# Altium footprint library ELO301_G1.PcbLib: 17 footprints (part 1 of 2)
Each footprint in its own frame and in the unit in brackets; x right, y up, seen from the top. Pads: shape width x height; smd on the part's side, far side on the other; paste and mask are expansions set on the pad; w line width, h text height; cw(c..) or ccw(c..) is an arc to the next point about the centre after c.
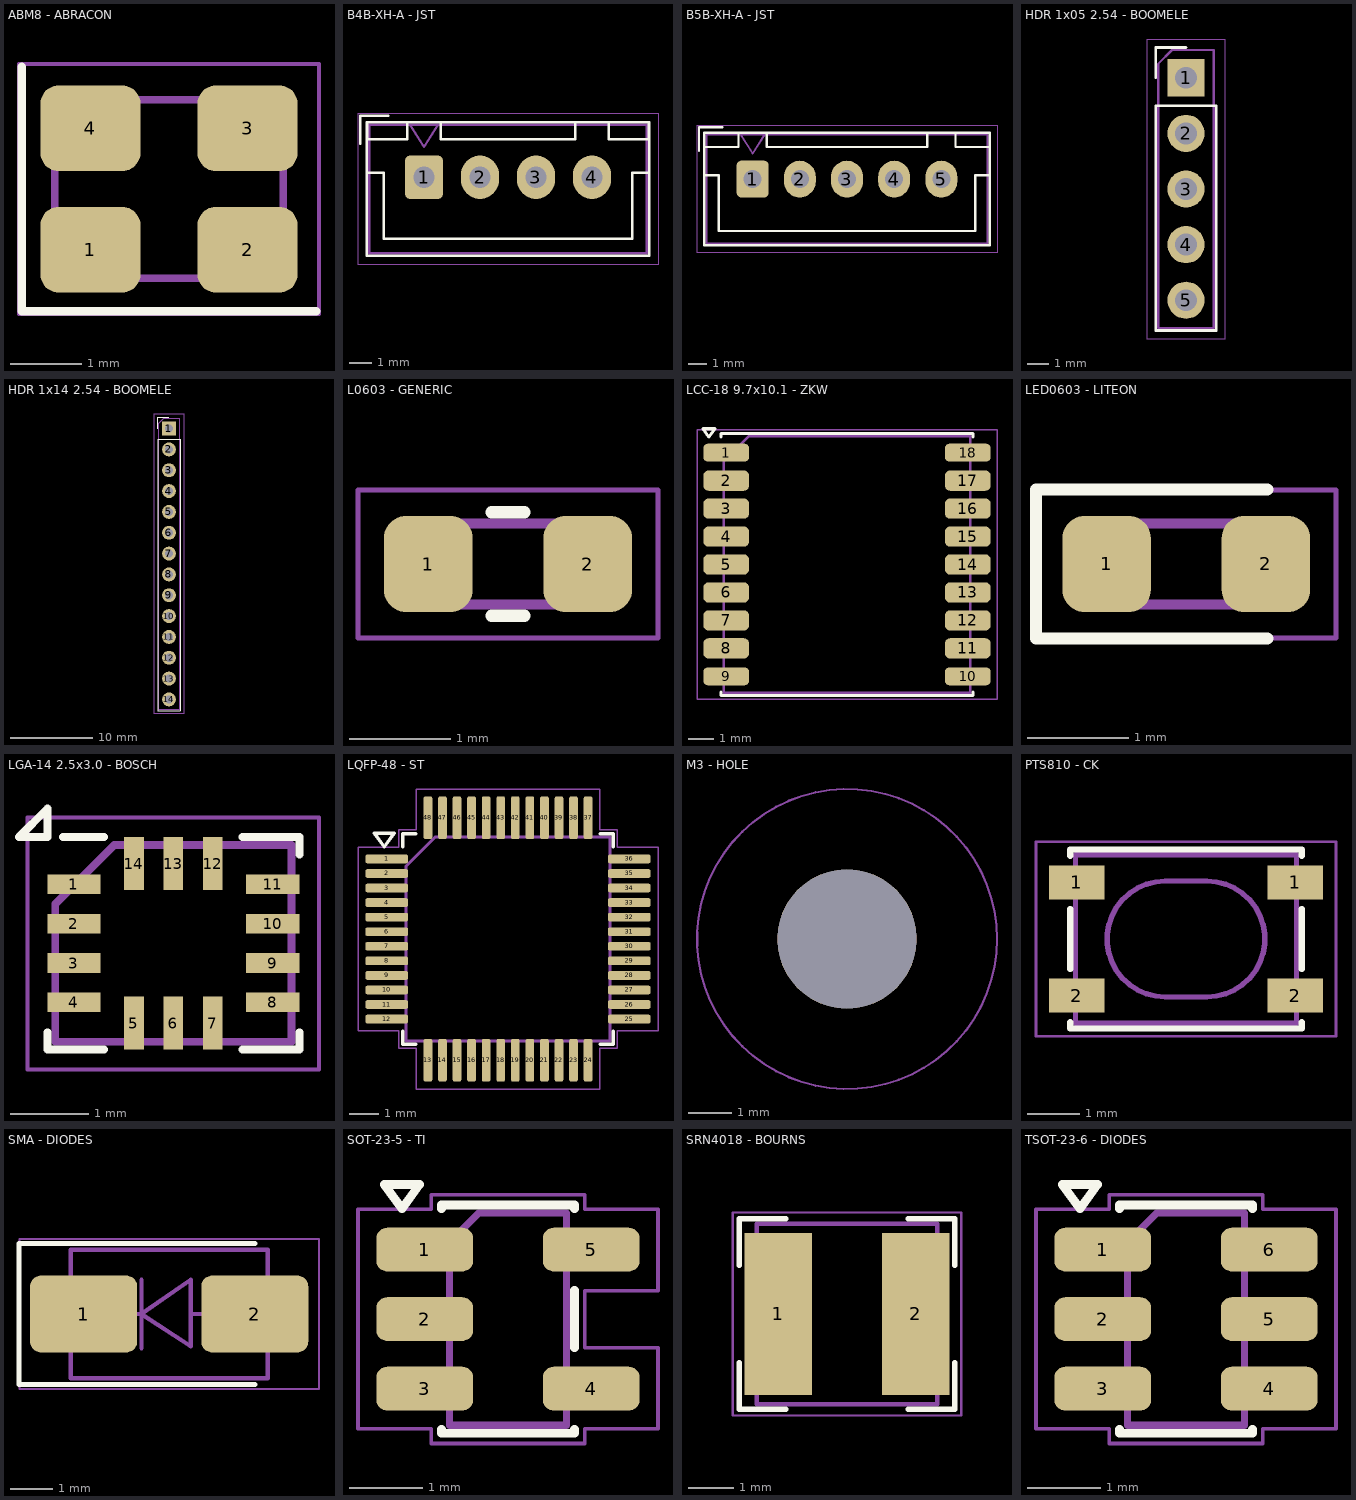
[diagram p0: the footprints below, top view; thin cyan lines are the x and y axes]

## ABM8 - ABRACON [mm] "Abracon ABM8G, Miniature Ceramic Crystal, 3.2x2.5mm package, SMD, http://www.abracon.com/Resonators/ABM8G.pdf"
pads (4):
  rrect42% 1.4x1.2 smd: 1(1268.9,1269.15) 2(1271.1,1269.15) 3(1271.1,1270.85) 4(1268.9,1270.85)
Top Overlay:
  lines w0.12: 1267.94,1271.71 1267.94,1268.29 1272.06,1268.29
Mechanical 13:
  lines w0.1: 1268.4,1269.375 1269.025,1268.75 1271.6,1268.75 1271.6,1271.25 1268.4,1271.25 1268.4,1269.375
Mechanical 15:
  lines w0.05: 1267.9,1268.25 1272.1,1268.25 1272.1,1271.75 1267.9,1271.75 1267.9,1268.25
Mechanical 29:
  text ".Designator" at 1269.492,1269.898 h0.25

## B4B-XH-A - JST [mm] "JST XH series connector, B4B-XH-A (http://www.jst-mfg.com/product/pdf/eng/eXH.pdf)"
pads (4):
  rrect29% 1.7x1.95 hole 0.95: 1(1270,1270)
  oval 1.7x1.95 hole 0.95: 2(1272.5,1270) 3(1275,1270) 4(1277.5,1270)
Top Overlay:
  lines w0.12: 1267.15,1271.5 1267.15,1272.75 1268.4,1272.75 ; 1267.45,1270.2 1268.2,1270.2 1268.2,1267.25 1273.75,1267.25 1279.3,1267.25 1279.3,1270.2 1280.05,1270.2 ; 1267.44,1266.49 1280.06,1266.49 1280.06,1272.46 1267.44,1272.46 1267.44,1266.49 ; 1267.45,1271.7 1269.25,1271.7 1269.25,1272.45 1267.45,1272.45 1267.45,1271.7 ; 1270.75,1271.7 1276.75,1271.7 1276.75,1272.45 1270.75,1272.45 1270.75,1271.7 ; 1278.25,1271.7 1280.05,1271.7 1280.05,1272.45 1278.25,1272.45 1278.25,1271.7
Mechanical 13:
  lines w0.1: 1269.375,1272.35 1270,1271.35 1270.625,1272.35 ; 1267.55,1266.6 1279.95,1266.6 1279.95,1272.35 1267.55,1272.35 1267.55,1266.6
Mechanical 15:
  lines w0.05: 1267.05,1266.1 1280.45,1266.1 1280.45,1272.85 1267.05,1272.85 1267.05,1266.1
Mechanical 29:
  text ".Designator" at 1269.492,1269.898 h0.25

## B5B-XH-A - JST [mm] "JST XH series connector, B5B-XH-A (http://www.jst-mfg.com/product/pdf/eng/eXH.pdf)"
pads (5):
  rrect29% 1.7x1.95 hole 0.95: 1(1270,1270)
  oval 1.7x1.95 hole 0.95: 2(1272.5,1270) 3(1275,1270) 4(1277.5,1270) 5(1280,1270)
Top Overlay:
  lines w0.12: 1267.15,1271.5 1267.15,1272.75 1268.4,1272.75 ; 1267.45,1270.2 1268.2,1270.2 1268.2,1267.25 1275,1267.25 1281.8,1267.25 1281.8,1270.2 1282.55,1270.2 ; 1267.44,1266.49 1282.56,1266.49 1282.56,1272.46 1267.44,1272.46 1267.44,1266.49 ; 1267.45,1271.7 1269.25,1271.7 1269.25,1272.45 1267.45,1272.45 1267.45,1271.7 ; 1270.75,1271.7 1279.25,1271.7 1279.25,1272.45 1270.75,1272.45 1270.75,1271.7 ; 1280.75,1271.7 1282.55,1271.7 1282.55,1272.45 1280.75,1272.45 1280.75,1271.7
Mechanical 13:
  lines w0.1: 1269.375,1272.35 1270,1271.35 1270.625,1272.35 ; 1267.55,1266.6 1282.45,1266.6 1282.45,1272.35 1267.55,1272.35 1267.55,1266.6
Mechanical 15:
  lines w0.05: 1267.05,1266.1 1282.95,1266.1 1282.95,1272.85 1267.05,1272.85 1267.05,1266.1
Mechanical 29:
  text ".Designator" at 1269.492,1269.898 h0.25

## HDR 1x05 2.54 - BOOMELE [mm] "Through hole straight pin header, 1x05, 2.54mm pitch, single row"
pads (5):
  rect 1.7x1.7 hole 1: 1(1270,1270)
  round 1.7 hole 1: 2(1270,1267.46) 3(1270,1264.92) 4(1270,1262.38) 5(1270,1259.84)
Top Overlay:
  lines w0.12: 1268.62,1270 1268.62,1271.38 1270,1271.38 ; 1268.62,1258.46 1268.62,1268.73 1271.38,1268.73 1271.38,1258.46 1268.62,1258.46
Mechanical 13:
  lines w0.1: 1268.73,1258.57 1268.73,1270.635 1269.365,1271.27 1271.27,1271.27 1271.27,1258.57 1268.73,1258.57
Mechanical 15:
  lines w0.05: 1268.23,1258.07 1271.77,1258.07 1271.77,1271.77 1268.23,1271.77 1268.23,1258.07
Mechanical 29:
  text ".Designator" at 1269.492,1269.898 h0.25

## HDR 1x14 2.54 - BOOMELE [mm] "Through hole straight pin header, 1x14, 2.54mm pitch, single row"
pads (14):
  rect 1.7x1.7 hole 1: 1(1270,1270)
  round 1.7 hole 1: 2(1270,1267.46) 3(1270,1264.92) 4(1270,1262.38) 5(1270,1259.84) 6(1270,1257.3) 7(1270,1254.76) 8(1270,1252.22) 9(1270,1249.68) 10(1270,1247.14) 11(1270,1244.6) 12(1270,1242.06) 13(1270,1239.52) 14(1270,1236.98)
Top Overlay:
  lines w0.12: 1268.62,1270 1268.62,1271.38 1270,1271.38 ; 1268.62,1235.6 1268.62,1268.73 1271.38,1268.73 1271.38,1235.6 1268.62,1235.6
Mechanical 13:
  lines w0.1: 1268.73,1235.71 1268.73,1270.635 1269.365,1271.27 1271.27,1271.27 1271.27,1235.71 1268.73,1235.71
Mechanical 15:
  lines w0.05: 1268.23,1235.2 1271.77,1235.2 1271.77,1271.78 1268.23,1271.78 1268.23,1235.2
Mechanical 29:
  text ".Designator" at 1269.492,1269.898 h0.25

## L0603 - GENERIC [mm] "Inductor SMD 0603 (1608 Metric), square (rectangular) end terminal, IPC-7351 nominal, (Body size source: http://www.tortai-tech.com/upload/download/2011102023233369053.pdf)"
pads (2):
  rrect50% 0.875x0.95 smd: 1(1269.212,1270) 2(1270.788,1270)
Top Overlay:
  lines w0.12: 1269.837,1269.49 1270.163,1269.49 ; 1269.837,1270.51 1270.163,1270.51
Mechanical 13:
  lines w0.1: 1269.2,1269.6 1270.8,1269.6 1270.8,1270.4 1269.2,1270.4 1269.2,1269.6
Mechanical 15:
  lines w0.05: 1268.52,1269.27 1271.48,1269.27 1271.48,1270.73 1268.52,1270.73 1268.52,1269.27
Mechanical 29:
  text ".Designator" at 1269.492,1269.898 h0.25

## LCC-18 9.7x10.1 - ZKW [mm] "ublox MAX 6/7/8, (https://www.u-blox.com/sites/default/files/MAX-8-M8-FW3_HardwareIntegrationManual_%28UBX-15030059%29.pdf)"
pads (18):
  rrect50% 1.8x0.7 smd: 1(1265.25,1274.4) 9(1265.25,1265.6) 10(1274.75,1265.6) 18(1274.75,1274.4)
  rrect50% 1.8x0.8 smd: 2(1265.25,1273.3) 3(1265.25,1272.2) 4(1265.25,1271.1) 5(1265.25,1270) 6(1265.25,1268.9) 7(1265.25,1267.8) 8(1265.25,1266.7) 11(1274.75,1266.7) 12(1274.75,1267.8) 13(1274.75,1268.9) 14(1274.75,1270) 15(1274.75,1271.1) 16(1274.75,1272.2) 17(1274.75,1273.3)
Top Overlay:
  lines w0.12: 1265.04,1264.99 1265.04,1264.84 1274.96,1264.84 1274.96,1264.99 ; 1265.04,1275.01 1265.04,1275.16 1274.96,1275.16 1274.96,1275.01 ; 1264.57,1275.01 1264.33,1275.34 1264.81,1275.34 1264.57,1275.01 ; 1264.57,1275.01 1264.57,1275.01
Mechanical 13:
  lines w0.1: 1265.15,1264.95 1265.15,1274.05 1266.15,1275.05 1274.85,1275.05 1274.85,1264.95 1265.15,1264.95
Mechanical 15:
  lines w0.05: 1264.1,1264.7 1264.1,1275.3 1275.9,1275.3 1275.9,1264.7 1264.1,1264.7
Mechanical 29:
  text ".Designator" at 1269.492,1269.898 h0.25

## LED0603 - LITEON [mm] "LED SMD 0603 (1608 Metric), square (rectangular) end terminal, IPC-7351 nominal, (Body size source: http://www.tortai-tech.com/upload/download/2011102023233369053.pdf)"
pads (2):
  rrect50% 0.875x0.95 smd: 1(1269.212,1270) 2(1270.788,1270)
Top Overlay:
  lines w0.12: 1270.8,1269.265 1268.515,1269.265 1268.515,1270.735 1270.8,1270.735
Mechanical 13:
  lines w0.1: 1269.2,1269.6 1269.2,1270.1 1269.5,1270.4 1270.8,1270.4 1270.8,1269.6 1269.2,1269.6
Mechanical 15:
  lines w0.05: 1268.52,1269.27 1271.48,1269.27 1271.48,1270.73 1268.52,1270.73 1268.52,1269.27
Mechanical 29:
  text ".Designator" at 1269.492,1269.898 h0.25

## LGA-14 2.5x3.0 - BOSCH [mm] "LGA-14 Bosch https://ae-bst.resource.bosch.com/media/_tech/media/datasheets/BST-BMI160-DS000-07.pdf"
pads (14):
  rect 0.675x0.25 smd: 1(1268.737,1270.75) 2(1268.737,1270.25) 3(1268.737,1269.75) 4(1268.737,1269.25) 8(1271.263,1269.25) 9(1271.263,1269.75) 10(1271.263,1270.25) 11(1271.263,1270.75)
  rect 0.25x0.675 smd: 5(1269.5,1268.988) 6(1270,1268.988) 7(1270.5,1268.988) 12(1270.5,1271.012) 13(1270,1271.012) 14(1269.5,1271.012)
Top Overlay:
  lines w0.1: 1268.4,1268.87 1268.4,1268.65 1269.12,1268.65 ; 1268.6,1271.35 1269.12,1271.35 ; 1270.88,1268.65 1271.6,1268.65 1271.6,1268.87 ; 1270.88,1271.35 1271.6,1271.35 1271.6,1271.13 ; 1268.4,1271.35 1268.04,1271.35 1268.4,1271.71 1268.4,1271.35 ; 1268.4,1271.35 1268.4,1271.35
Mechanical 13:
  lines w0.1: 1268.5,1268.75 1268.5,1270.5 1269.25,1271.25 1271.5,1271.25 1271.5,1268.75 1268.5,1268.75
Mechanical 15:
  lines w0.05: 1268.15,1268.4 1268.15,1271.6 1271.85,1271.6 1271.85,1268.4 1268.15,1268.4
Mechanical 29:
  text ".Designator" at 1269.492,1269.898 h0.25

## LQFP-48 - ST [mm] "LQFP, 48 Pin (JEDEC MS-026 variation BBC, 1.40mm body thickness, https://www.jedec.org/document_search?search_api_views_fulltext=MS-026, https://www.analog.com/media/en/package-pcb-resources/package/pkg_pdf/ltc-legacy-lqfp/05081760_a_lx48.pdf)"
pads (48):
  rrect50% 1.475x0.3 smd: 1(1265.837,1272.75) 2(1265.837,1272.25) 3(1265.837,1271.75) 4(1265.837,1271.25) 5(1265.837,1270.75) 6(1265.837,1270.25) 7(1265.837,1269.75) 8(1265.837,1269.25) 9(1265.837,1268.75) 10(1265.837,1268.25) 11(1265.837,1267.75) 12(1265.837,1267.25) 25(1274.163,1267.25) 26(1274.163,1267.75) 27(1274.163,1268.25) 28(1274.163,1268.75) 29(1274.163,1269.25) 30(1274.163,1269.75) 31(1274.163,1270.25) 32(1274.163,1270.75) 33(1274.163,1271.25) 34(1274.163,1271.75) 35(1274.163,1272.25) 36(1274.163,1272.75)
  rrect50% 0.3x1.475 smd: 13(1267.25,1265.837) 14(1267.75,1265.837) 15(1268.25,1265.837) 16(1268.75,1265.837) 17(1269.25,1265.837) 18(1269.75,1265.837) 19(1270.25,1265.837) 20(1270.75,1265.837) 21(1271.25,1265.837) 22(1271.75,1265.837) 23(1272.25,1265.837) 24(1272.75,1265.837) 37(1272.75,1274.163) 38(1272.25,1274.163) 39(1271.75,1274.163) 40(1271.25,1274.163) 41(1270.75,1274.163) 42(1270.25,1274.163) 43(1269.75,1274.163) 44(1269.25,1274.163) 45(1268.75,1274.163) 46(1268.25,1274.163) 47(1267.75,1274.163) 48(1267.25,1274.163)
Top Overlay:
  lines w0.12: 1266.39,1266.84 1266.39,1266.39 1266.84,1266.39 ; 1266.39,1273.16 1266.39,1273.61 1266.84,1273.61 ; 1273.16,1266.39 1273.61,1266.39 1273.61,1266.84 ; 1273.16,1273.61 1273.61,1273.61 1273.61,1273.16 ; 1265.41,1273.63 1266.09,1273.63 1265.75,1273.16 1265.41,1273.63
Mechanical 13:
  lines w0.1: 1266.5,1266.5 1266.5,1272.5 1267.5,1273.5 1273.5,1273.5 1273.5,1266.5 1266.5,1266.5
Mechanical 15:
  lines w0.05: 1264.85,1266.85 1266.25,1266.85 1266.25,1266.25 1266.85,1266.25 1266.85,1264.85 1273.15,1264.85 1273.15,1266.25 1273.75,1266.25 1273.75,1266.85 1275.15,1266.85 1275.15,1273.15 1273.75,1273.15 1273.75,1273.75 1273.15,1273.75 1273.15,1275.15 1266.85,1275.15 1266.85,1273.75 1266.25,1273.75 1266.25,1273.15 1264.85,1273.15 1264.85,1266.85
Mechanical 29:
  text ".Designator" at 1269.492,1269.898 h0.25

## M3 - HOLE [mm] "Mounting Hole 3.2mm, M3, no annular, generated by kicad-footprint-generator mountinghole.py"
pads (1):
  round 3.2 hole 3.2 unplated: ""(1270,1270)
Mechanical 15:
  circle w0.05: c1270,1270 r3.45
Mechanical 29:
  text ".Designator" at 1269.492,1269.898 h0.25

## PTS810 - CK [mm] "C&K Components, PTS 810 Series, Microminiature SMT Top Actuated, http://www.ckswitches.com/media/1476/pts810.pdf"
pads (4):
  rect 1.05x0.65 smd: 1(1267.925,1271.075) 1(1272.075,1271.075) 2(1267.925,1268.925) 2(1272.075,1268.925)
Top Overlay:
  lines w0.12: 1267.8,1268.42 1267.8,1268.3 1272.2,1268.3 1272.2,1268.42 ; 1267.8,1269.43 1267.8,1270.57 ; 1267.8,1271.58 1267.8,1271.7 1272.2,1271.7 1272.2,1271.58 ; 1272.2,1269.43 1272.2,1270.57
Mechanical 13:
  lines w0.1: 1267.9,1268.4 1267.9,1271.6 1272.1,1271.6 1272.1,1268.4 1267.9,1268.4 ; 1269.6,1268.9 1270.4,1268.9 ccw(c1270.4,1270) 1270.4,1271.1 1269.6,1271.1 ccw(c1269.6,1270) 1269.6,1268.9
Mechanical 15:
  lines w0.05: 1267.15,1268.15 1267.15,1271.85 1272.85,1271.85 1272.85,1268.15 1267.15,1268.15
Mechanical 29:
  text ".Designator" at 1269.492,1269.898 h0.25

## SMA - DIODES [mm] "Diode SMA (DO-214AC)"
pads (2):
  rrect28% 2.5x1.8 smd: 1(1268,1270) 2(1272,1270)
Top Overlay:
  lines w0.12: 1272,1268.35 1266.49,1268.35 1266.49,1271.65 1272,1271.65
Mechanical 13:
  lines w0.1: 1268.449,1269.999 1269.351,1269.999 ; 1269.351,1269.199 1269.351,1270.799 ; 1270.501,1269.999 1271.499,1269.999 ; 1269.351,1269.999 1270.501,1270.799 1270.501,1269.25 1269.351,1269.999 ; 1267.7,1268.5 1267.7,1271.5 1272.3,1271.5 1272.3,1268.5 1267.7,1268.5
Mechanical 15:
  lines w0.05: 1266.5,1268.25 1266.5,1271.75 1273.5,1271.75 1273.5,1268.25 1266.5,1268.25
Mechanical 29:
  text ".Designator" at 1269.492,1269.898 h0.25

## SOT-23-5 - TI [mm] "SOT, 5 Pin (JEDEC MO-178 Var AA https://www.jedec.org/document_search?search_api_views_fulltext=MO-178)"
pads (5):
  rrect50% 1.325x0.6 smd: 1(1268.863,1270.95) 2(1268.863,1270) 3(1268.863,1269.05) 4(1271.137,1269.05) 5(1271.137,1270.95)
Top Overlay:
  lines w0.12: 1269.09,1268.49 1269.09,1268.44 1270.91,1268.44 1270.91,1268.49 ; 1269.09,1271.51 1269.09,1271.56 1270.91,1271.56 1270.91,1271.51 ; 1270.91,1269.61 1270.91,1270.39 ; 1268.31,1271.84 1268.55,1271.51 1268.79,1271.84 1268.31,1271.84
Mechanical 13:
  lines w0.1: 1269.2,1268.55 1270.8,1268.55 1270.8,1271.45 1269.6,1271.45 1269.2,1271.05 1269.2,1268.55
Mechanical 15:
  lines w0.05: 1267.95,1268.5 1267.95,1271.5 1268.95,1271.5 1268.95,1271.7 1271.05,1271.7 1271.05,1271.5 1272.05,1271.5 1272.05,1270.39 1271.05,1270.39 1271.05,1269.61 1272.05,1269.61 1272.05,1268.5 1271.05,1268.5 1271.05,1268.3 1268.95,1268.3 1268.95,1268.5 1267.95,1268.5
Mechanical 29:
  text ".Designator" at 1269.492,1269.898 h0.25

## SRN4018 - BOURNS [mm] "Bourns SRN4018 series SMD inductor, https://www.bourns.com/docs/Product-Datasheets/SRN4018.pdf"
pads (2):
  rect 1.5x3.6 smd: 1(1268.475,1270) 2(1271.525,1270)
Top Overlay:
  lines w0.12: 1267.615,1268.915 1267.615,1267.89 1268.64,1267.89 ; 1267.615,1271.085 1267.615,1272.11 1268.64,1272.11 ; 1271.36,1267.89 1272.385,1267.89 1272.385,1268.915 ; 1271.36,1272.11 1272.385,1272.11 1272.385,1271.085
Mechanical 13:
  lines w0.1: 1268,1268 1268,1272 1272,1272 1272,1268 1268,1268
Mechanical 15:
  lines w0.05: 1267.47,1267.75 1267.47,1272.25 1272.53,1272.25 1272.53,1267.75 1267.47,1267.75
Mechanical 29:
  text ".Designator" at 1269.492,1269.898 h0.25

## TSOT-23-6 - DIODES [mm] "TSOT, 6 Pin (https://www.jedec.org/sites/default/files/docs/MO-193D.pdf variant AA)"
pads (6):
  rrect50% 1.325x0.6 smd: 1(1268.863,1270.95) 2(1268.863,1270) 3(1268.863,1269.05) 4(1271.137,1269.05) 5(1271.137,1270) 6(1271.137,1270.95)
Top Overlay:
  lines w0.12: 1269.09,1268.49 1269.09,1268.44 1270.91,1268.44 1270.91,1268.49 ; 1269.09,1271.51 1269.09,1271.56 1270.91,1271.56 1270.91,1271.51 ; 1268.31,1271.84 1268.55,1271.51 1268.79,1271.84 1268.31,1271.84
Mechanical 13:
  lines w0.1: 1269.2,1268.55 1270.8,1268.55 1270.8,1271.45 1269.6,1271.45 1269.2,1271.05 1269.2,1268.55
Mechanical 15:
  lines w0.05: 1267.95,1268.5 1267.95,1271.5 1268.95,1271.5 1268.95,1271.7 1271.05,1271.7 1271.05,1271.5 1272.05,1271.5 1272.05,1268.5 1271.05,1268.5 1271.05,1268.3 1268.95,1268.3 1268.95,1268.5 1267.95,1268.5
Mechanical 29:
  text ".Designator" at 1269.492,1269.898 h0.25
